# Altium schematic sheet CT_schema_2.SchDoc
size 276 x 169 mm
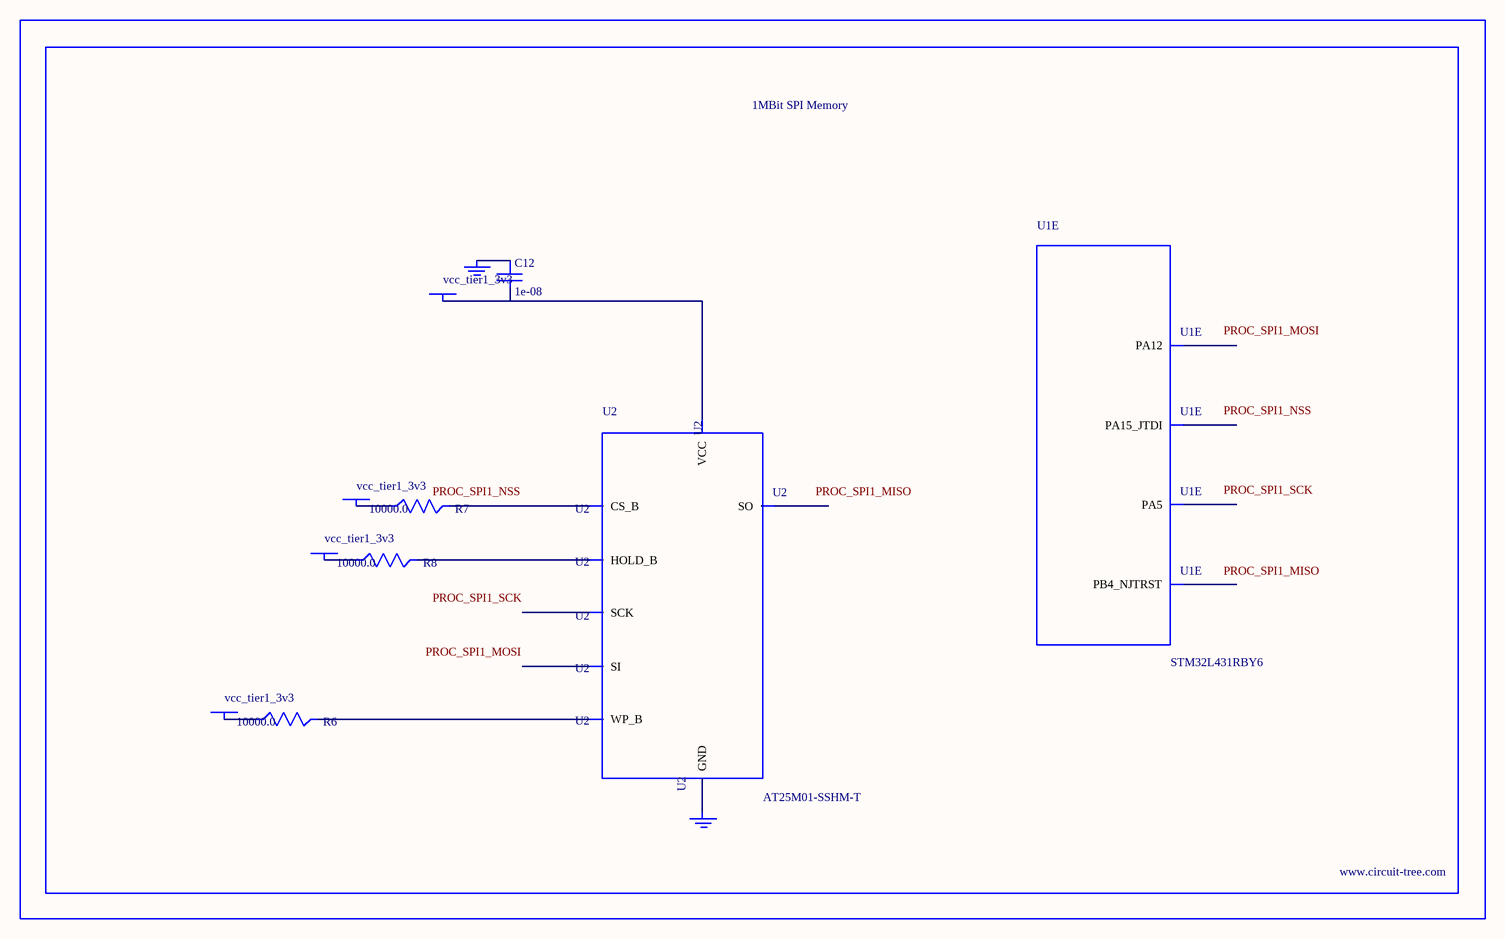
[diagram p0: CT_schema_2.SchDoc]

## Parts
BORDER1  (no value)
C12  1e-08  [C0402]
GND_INSTANCE_1_0  (no value)
GND_INSTANCE_1_1  (no value)
POWER_INSTANCE_1_0  vcc_tier1_3v3
POWER_INSTANCE_1_1  vcc_tier1_3v3
POWER_INSTANCE_1_2  vcc_tier1_3v3
POWER_INSTANCE_1_3  vcc_tier1_3v3
R6  10000.0  [R0603]
R7  10000.0  [R0603]
R8  10000.0  [R0603]
U1  STM32L431RBY6  [WLCSP64]  (part E of 7)
U2  AT25M01-SSHM-T  [SOIC-8]

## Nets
NetC12_1: C12.1 GND_INSTANCE_1_0.0(GND)
NetC12_2: C12.2 POWER_INSTANCE_1_3.0(PWR) U2.8(VCC)
NetGND_INSTANCE_1_1_0: GND_INSTANCE_1_1.0(GND) U2.4(GND)
NetPOWER_INSTANCE_1_0_0: POWER_INSTANCE_1_0.0(PWR) R7.1
NetPOWER_INSTANCE_1_1_0: POWER_INSTANCE_1_1.0(PWR) R6.1
NetPOWER_INSTANCE_1_2_0: POWER_INSTANCE_1_2.0(PWR) R8.1
NetR6_2: R6.2 U2.3(WP_B)
NetR7_2: R7.2 U2.1(CS_B)
NetR8_2: R8.2 U2.7(HOLD_B)

Not connected (* = marked no-connect by the designer): U1 A2(PA15_JTDI) B4(PB4_NJTRST) C1(PA12) F5(PA5); U2 2(SO) 5(SI) 6(SCK)

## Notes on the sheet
- Labels drawn without touching a wire or pin: PROC_SPI1_MISO, PROC_SPI1_MOSI, PROC_SPI1_NSS, PROC_SPI1_SCK

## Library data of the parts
BORDER1 = BORDER_PAGE1
C12 = C0402C103K3RAC
GND_INSTANCE_1_0 GND_INSTANCE_1_1 = GND
POWER_INSTANCE_1_0-POWER_INSTANCE_1_3 = PWR
R6-R8 = RC0603JR-0710KL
